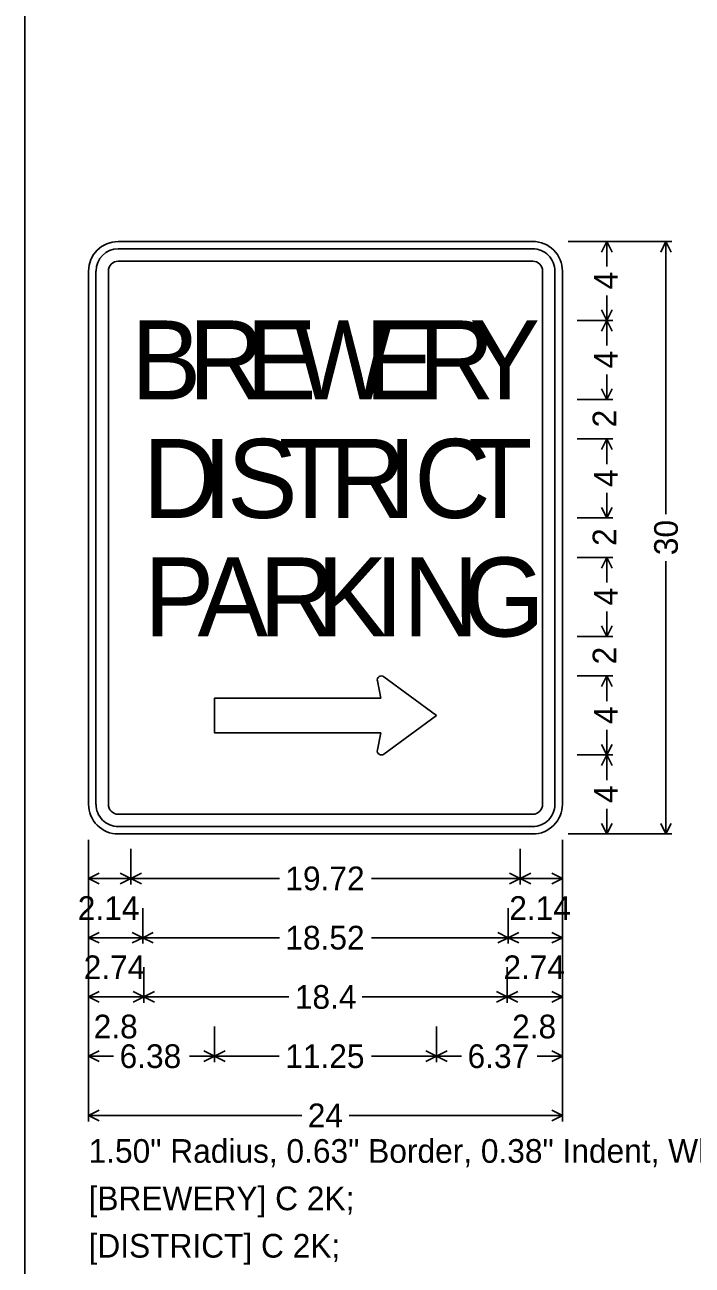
# Model space of a CAD drawing. Extents: x 1822205 to 1824724, y 710141 to 711863.
# Drawn here: x 1823510 to 1823791, y 710655 to 711177 of the extents above; entities that cross this region are included whole.
import ezdxf

# ---------------------------------------------------------------- set-up
doc = ezdxf.new("R2010")
doc.units = 0
doc.layers.add('PM_P_Cells', color=7, linetype='Continuous')

msp = doc.modelspace()

# ---------------------------------------------------------------- linework, layer by layer
at = {"layer": 'PM_P_Cells'}
for p, q in [((1823509.74, 711216.46), (1823509.74, 710166.46)), ((1823723.7, 711085.98), (1823549.09, 711085.98)), ((1823782.33, 711085.98), (1823738.67, 711085.98)), ((1823757.38, 711085.98), (1823742.41, 711085.98)), ((1823752.65, 711081.52), (1823754.89, 711085.98)), ((1823754.89, 711075.42), (1823754.89, 711085.98)), ((1823757.12, 711081.52), (1823754.89, 711085.98)), ((1823777.6, 711081.52), (1823779.83, 711085.98)), ((1823779.83, 710971.12), (1823779.83, 711085.98)), ((1823782.06, 711081.52), (1823779.83, 711085.98)), ((1823536.61, 711073.51), (1823536.61, 710849)), ((1823736.18, 710849), (1823736.18, 711073.51)), ((1823754.89, 711063.28), (1823754.89, 711052.72)), ((1823752.65, 711057.19), (1823754.89, 711052.72)), ((1823757.12, 711057.19), (1823754.89, 711052.72)), ((1823757.38, 711052.72), (1823742.41, 711052.72)), ((1823752.65, 711048.26), (1823754.89, 711052.72)), ((1823754.89, 711042.16), (1823754.89, 711052.72)), ((1823757.12, 711048.26), (1823754.89, 711052.72)), ((1823754.89, 711030.02), (1823754.89, 711019.46)), ((1823752.65, 711023.93), (1823754.89, 711019.46)), ((1823757.12, 711023.93), (1823754.89, 711019.46)), ((1823757.38, 711019.46), (1823742.41, 711019.46)), ((1823757.38, 711002.83), (1823742.41, 711002.83)), ((1823752.65, 710998.36), (1823754.89, 711002.83)), ((1823754.89, 710992.27), (1823754.89, 711002.83)), ((1823757.12, 710998.36), (1823754.89, 711002.83)), ((1823754.89, 710980.13), (1823754.89, 710969.57)), ((1823752.65, 710974.03), (1823754.89, 710969.57)), ((1823757.12, 710974.03), (1823754.89, 710969.57)), ((1823757.38, 710969.57), (1823742.41, 710969.57)), ((1823757.38, 710952.94), (1823742.41, 710952.94)), ((1823752.65, 710948.47), (1823754.89, 710952.94)), ((1823754.89, 710942.38), (1823754.89, 710952.94)), ((1823757.12, 710948.47), (1823754.89, 710952.94)), ((1823779.83, 710951.39), (1823779.83, 710836.53)), ((1823754.89, 710930.24), (1823754.89, 710919.68)), ((1823752.65, 710924.14), (1823754.89, 710919.68)), ((1823757.12, 710924.14), (1823754.89, 710919.68)), ((1823757.38, 710919.68), (1823742.41, 710919.68)), ((1823757.38, 710903.05), (1823742.41, 710903.05)), ((1823752.65, 710898.58), (1823754.89, 710903.05)), ((1823754.89, 710892.49), (1823754.89, 710903.05)), ((1823757.12, 710898.58), (1823754.89, 710903.05)), ((1823754.89, 710880.35), (1823754.89, 710869.79)), ((1823752.65, 710874.25), (1823754.89, 710869.79)), ((1823757.12, 710874.25), (1823754.89, 710869.79)), ((1823757.38, 710869.79), (1823742.41, 710869.79)), ((1823757.38, 710869.79), (1823742.41, 710869.79)), ((1823752.65, 710865.32), (1823754.89, 710869.79)), ((1823754.89, 710859.23), (1823754.89, 710869.79)), ((1823757.12, 710865.32), (1823754.89, 710869.79)), ((1823754.89, 710847.09), (1823754.89, 710836.53)), ((1823752.65, 710840.99), (1823754.89, 710836.53)), ((1823757.12, 710840.99), (1823754.89, 710836.53)), ((1823777.6, 710840.99), (1823779.83, 710836.53)), ((1823782.06, 710840.99), (1823779.83, 710836.53)), ((1823549.09, 710836.53), (1823723.7, 710836.53)), ((1823782.33, 710836.53), (1823738.67, 710836.53)), ((1823757.38, 710836.53), (1823742.41, 710836.53)), ((1823536.61, 710715.54), (1823536.61, 710834.03)), ((1823536.61, 710815.32), (1823536.61, 710830.29)), ((1823554.41, 710815.32), (1823554.41, 710830.29)), ((1823718.38, 710815.32), (1823718.38, 710830.29)), ((1823718.38, 710815.32), (1823718.38, 710830.29)), ((1823736.18, 710715.54), (1823736.18, 710834.03)), ((1823736.18, 710815.32), (1823736.18, 710830.29)), ((1823541.08, 710820.05), (1823536.61, 710817.82)), ((1823549.95, 710820.05), (1823554.41, 710817.82)), ((1823558.87, 710820.05), (1823554.41, 710817.82)), ((1823713.92, 710820.05), (1823718.38, 710817.82)), ((1823722.84, 710820.05), (1823718.38, 710817.82)), ((1823731.71, 710820.05), (1823736.18, 710817.82)), ((1823545.51, 710817.82), (1823536.61, 710817.82)), ((1823541.08, 710815.59), (1823536.61, 710817.82)), ((1823545.51, 710817.82), (1823554.41, 710817.82)), ((1823549.95, 710815.59), (1823554.41, 710817.82)), ((1823617, 710817.82), (1823554.41, 710817.82)), ((1823558.87, 710815.59), (1823554.41, 710817.82)), ((1823655.79, 710817.82), (1823718.38, 710817.82)), ((1823713.92, 710815.59), (1823718.38, 710817.82)), ((1823727.28, 710817.82), (1823718.38, 710817.82)), ((1823722.84, 710815.59), (1823718.38, 710817.82)), ((1823727.28, 710817.82), (1823736.18, 710817.82)), ((1823731.71, 710815.59), (1823736.18, 710817.82)), ((1823536.61, 710790.38), (1823536.61, 710805.35)), ((1823559.4, 710790.38), (1823559.4, 710805.35)), ((1823713.39, 710790.38), (1823713.39, 710805.35)), ((1823713.39, 710790.38), (1823713.39, 710805.35)), ((1823736.18, 710790.38), (1823736.18, 710805.35)), ((1823541.08, 710795.1), (1823536.61, 710792.87)), ((1823554.93, 710795.1), (1823559.4, 710792.87)), ((1823563.86, 710795.1), (1823559.4, 710792.87)), ((1823708.93, 710795.1), (1823713.39, 710792.87)), ((1823717.86, 710795.1), (1823713.39, 710792.87)), ((1823731.71, 710795.1), (1823736.18, 710792.87)), ((1823548.01, 710792.87), (1823536.61, 710792.87)), ((1823541.08, 710790.65), (1823536.61, 710792.87)), ((1823548.01, 710792.87), (1823559.4, 710792.87)), ((1823554.93, 710790.65), (1823559.4, 710792.87)), ((1823617, 710792.87), (1823559.4, 710792.87)), ((1823563.86, 710790.65), (1823559.4, 710792.87)), ((1823655.79, 710792.87), (1823713.39, 710792.87)), ((1823708.93, 710790.65), (1823713.39, 710792.87)), ((1823724.78, 710792.87), (1823713.39, 710792.87)), ((1823717.86, 710790.65), (1823713.39, 710792.87)), ((1823724.78, 710792.87), (1823736.18, 710792.87)), ((1823731.71, 710790.65), (1823736.18, 710792.87)), ((1823536.61, 710765.43), (1823536.61, 710780.4)), ((1823559.9, 710765.43), (1823559.9, 710780.4)), ((1823712.89, 710765.43), (1823712.89, 710780.4)), ((1823712.89, 710765.43), (1823712.89, 710780.4)), ((1823736.18, 710765.43), (1823736.18, 710780.4)), ((1823541.08, 710770.16), (1823536.61, 710767.93)), ((1823548.25, 710767.93), (1823536.61, 710767.93)), ((1823541.08, 710765.7), (1823536.61, 710767.93)), ((1823548.25, 710767.93), (1823559.9, 710767.93)), ((1823555.43, 710770.16), (1823559.9, 710767.93)), ((1823555.43, 710765.7), (1823559.9, 710767.93)), ((1823564.36, 710770.16), (1823559.9, 710767.93)), ((1823621, 710767.93), (1823559.9, 710767.93)), ((1823564.36, 710765.7), (1823559.9, 710767.93)), ((1823651.79, 710767.93), (1823712.89, 710767.93)), ((1823708.43, 710770.16), (1823712.89, 710767.93)), ((1823708.43, 710765.7), (1823712.89, 710767.93)), ((1823717.36, 710770.16), (1823712.89, 710767.93)), ((1823724.54, 710767.93), (1823712.89, 710767.93)), ((1823717.36, 710765.7), (1823712.89, 710767.93)), ((1823724.54, 710767.93), (1823736.18, 710767.93)), ((1823731.71, 710770.16), (1823736.18, 710767.93)), ((1823731.71, 710765.7), (1823736.18, 710767.93)), ((1823536.61, 710740.49), (1823536.61, 710755.46)), ((1823589.62, 710740.49), (1823589.62, 710755.46)), ((1823683.17, 710740.49), (1823683.17, 710755.46)), ((1823683.17, 710740.49), (1823683.17, 710755.46)), ((1823736.18, 710740.49), (1823736.18, 710755.46)), ((1823541.08, 710745.21), (1823536.61, 710742.98)), ((1823547.17, 710742.98), (1823536.61, 710742.98)), ((1823541.08, 710740.75), (1823536.61, 710742.98)), ((1823579.06, 710742.98), (1823589.62, 710742.98)), ((1823585.16, 710745.21), (1823589.62, 710742.98)), ((1823585.16, 710740.75), (1823589.62, 710742.98)), ((1823594.08, 710745.21), (1823589.62, 710742.98)), ((1823616.95, 710742.98), (1823589.62, 710742.98)), ((1823594.08, 710740.75), (1823589.62, 710742.98)), ((1823655.84, 710742.98), (1823683.17, 710742.98)), ((1823678.7, 710745.21), (1823683.17, 710742.98)), ((1823678.7, 710740.75), (1823683.17, 710742.98)), ((1823687.63, 710745.21), (1823683.17, 710742.98)), ((1823693.75, 710742.98), (1823683.17, 710742.98)), ((1823687.63, 710740.75), (1823683.17, 710742.98)), ((1823725.59, 710742.98), (1823736.18, 710742.98)), ((1823731.71, 710745.21), (1823736.18, 710742.98)), ((1823731.71, 710740.75), (1823736.18, 710742.98)), ((1823541.08, 710720.27), (1823536.61, 710718.04)), ((1823626.46, 710718.04), (1823536.61, 710718.04)), ((1823541.08, 710715.81), (1823536.61, 710718.04)), ((1823646.33, 710718.04), (1823736.18, 710718.04)), ((1823731.71, 710720.27), (1823736.18, 710718.04)), ((1823731.71, 710715.81), (1823736.18, 710718.04))]:
    msp.add_line(p, q, dxfattribs=at)
for points in [[(1823723.7, 711082.86), (1823549.09, 711082.86)], [(1823549.09, 711077.67), (1823723.7, 711077.67)], [(1823539.73, 711073.51), (1823539.73, 710849)], [(1823544.93, 710849), (1823544.93, 711073.51)], [(1823727.86, 711073.51), (1823727.86, 710849)], [(1823733.06, 710849), (1823733.06, 711073.51)], [(1823658.26, 710900.95), (1823659.78, 710893.69)], [(1823683.17, 710886.42), (1823660.96, 710902.74)], [(1823589.62, 710879.14), (1823589.62, 710893.69), (1823659.78, 710893.69)], [(1823660.96, 710870.1), (1823683.17, 710886.42), (1823683.17, 710886.42)], [(1823659.78, 710879.14), (1823589.62, 710879.14), (1823589.62, 710879.14)], [(1823659.78, 710879.14), (1823658.26, 710871.89)], [(1823723.7, 710844.84), (1823549.09, 710844.84)], [(1823549.09, 710839.65), (1823723.7, 710839.65)]]:
    msp.add_lwpolyline(points, dxfattribs=at)
for centre, radius, start, end in [((1823549.09, 711073.51), 12.47, 90.0002, 179.9998), ((1823723.7, 711073.51), 12.47, 0, 90.0002), ((1823549.09, 711073.51), 9.35, 90.0002, 179.9998), ((1823723.7, 711073.51), 9.35, 0, 90.0002), ((1823549.09, 711073.51), 4.16, 90.0002, 179.9998), ((1823723.7, 711073.51), 4.16, 0, 90.0002), ((1823659.97, 710901.3), 1.75, 55.2472, 191.8555), ((1823659.97, 710871.53), 1.75, 168.1448, 304.7528), ((1823549.09, 710849), 12.47, 179.9998, 270.0001), ((1823549.09, 710849), 9.35, 179.9998, 270.0001), ((1823549.09, 710849), 4.16, 179.9998, 270.0001), ((1823723.7, 710849), 12.47, 270.0001, 0.0003), ((1823723.7, 710849), 9.35, 270.0001, 0.0003), ((1823723.7, 710849), 4.16, 270.0001, 0.0003)]:
    msp.add_arc(centre, radius, start, end, dxfattribs=at)

# ---------------------------------------------------------------- texts
for s, height, p in [('4', 9.98, (1823759.47, 711065.78)), ('4', 9.98, (1823759.47, 711032.52)), ('2', 9.98, (1823758.91, 711007.69)), ('4', 9.98, (1823759.47, 710982.62)), ('30', 9.978, (1823784.82, 710953.89)), ('2', 9.98, (1823758.91, 710957.8)), ('4', 9.98, (1823759.47, 710932.73)), ('2', 9.98, (1823758.91, 710907.91)), ('4', 9.98, (1823759.47, 710882.84)), ('4', 9.98, (1823759.47, 710849.58))]:
    msp.add_text(s, height=height, rotation=90.0002, dxfattribs=at).set_placement(p)
for s, height, p in [('B', 33.26, (1823554.41, 711019.46)), ('R', 33.26, (1823578.69, 711019.46)), ('E', 33.26, (1823602.97, 711019.46)), ('W', 33.26, (1823622.92, 711019.46)), ('E', 33.26, (1823652.86, 711019.46)), ('R', 33.26, (1823675.48, 711019.46)), ('Y', 33.26, (1823697.1, 711019.46)), ('D', 33.26, (1823559.4, 710969.57)), ('I', 33.26, (1823584.67, 710969.57)), ('S', 33.26, (1823594.99, 710969.57)), ('T', 33.26, (1823616.6, 710969.57)), ('R', 33.26, (1823638.22, 710969.57)), ('I', 33.26, (1823662.5, 710969.57)), ('C', 33.26, (1823673.81, 710969.57)), ('T', 33.26, (1823696.43, 710969.57)), ('P', 33.26, (1823559.9, 710919.68)), ('A', 33.26, (1823582.51, 710919.68)), ('R', 33.26, (1823608.46, 710919.68)), ('K', 33.26, (1823632.74, 710919.68)), ('I', 33.26, (1823657.02, 710919.68)), ('N', 33.26, (1823668.99, 710919.68)), ('G', 33.26, (1823694.27, 710919.68)), ('19.72', 9.978, (1823619.49, 710812.83)), ('2.14', 9.978, (1823532.06, 710800.36)), ('2.14', 9.978, (1823713.83, 710800.36)), ('18.52', 9.978, (1823619.49, 710787.88)), ('2.74', 9.978, (1823534.55, 710775.41)), ('2.74', 9.978, (1823711.33, 710775.41)), ('18.4', 9.978, (1823623.49, 710762.94)), ('2.8', 9.978, (1823538.75, 710750.47)), ('2.8', 9.978, (1823715.03, 710750.47)), ('6.38', 9.978, (1823549.67, 710737.99)), ('11.25', 9.978, (1823619.44, 710737.99)), ('6.37', 9.978, (1823696.25, 710737.99)), ('24', 9.978, (1823628.95, 710713.05)), ('1.50" Radius, 0.63" Border, 0.38" Indent, White on Brown; ', 9.9781, (1823536.61, 710698.08)), ('[BREWERY] C 2K; ', 9.9781, (1823536.61, 710678.12)), ('[DISTRICT] C 2K; ', 9.9781, (1823536.61, 710658.17))]:
    msp.add_text(s, height=height, dxfattribs=at).set_placement(p)

doc.saveas('drawing.dxf')
